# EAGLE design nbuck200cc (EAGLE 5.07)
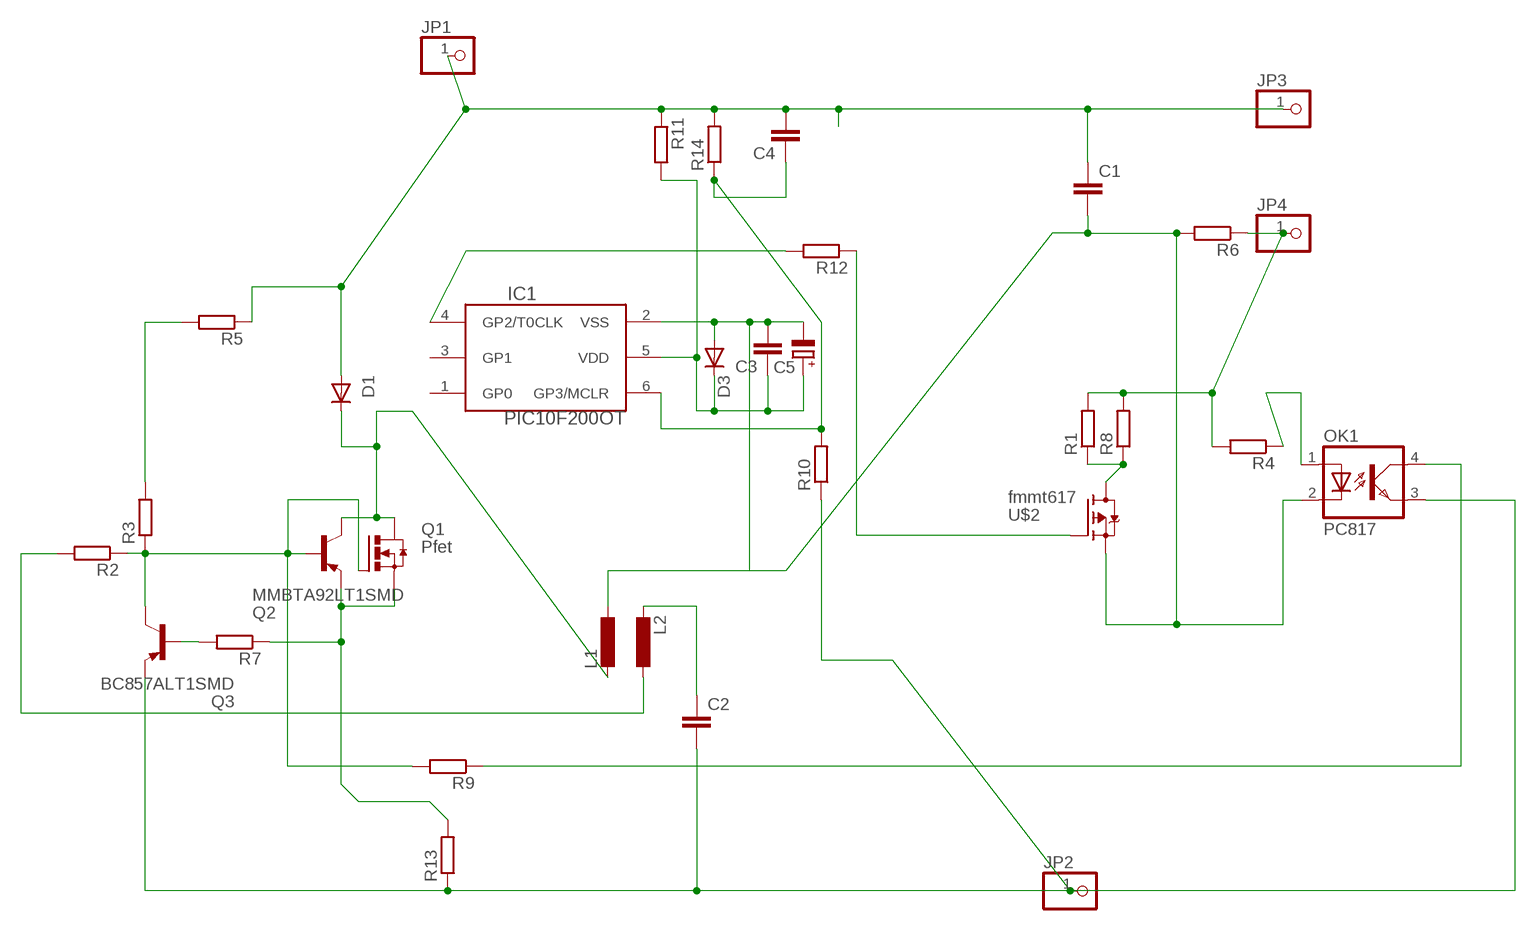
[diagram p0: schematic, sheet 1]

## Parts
C1  C-EU025-025X050  [C025-025X050]
C2  C-EUC0805  [C0805]
C3  C-EUC0805  [C0805]
C4  C-EUC1206  [C1206]
C5  CPOL-EUE2.5-5  [E2,5-5]
D1  DIODE-SMC  [SMC]
D3  DIODE-MINIMELF  [MINIMELF]
IC1  PIC10F200OT  [SOT23-6]
JP1  PINHD-1X11MM6  [1X1MM8]
JP2  PINHD-1X11MM6  [1X1MM8]
JP3  PINHD-1X11MM6  [1X1MM8]
JP4  PINHD-1X11MM6  [1X1MM8]
L1  L-EU0204/5  [0204/5]
L2  L-EU0207/10  [0207/10]
OK1  PC817  [DIL04]
Q1  Pfet  N-HEXFET_DPAK-  [TO252]
Q2  MMBTA92LT1SMD  [SOT23-BEC]
Q3  BC857ALT1SMD  [SOT23-BEC]
R1  R-EU_R2010  [R2010]
R2  R-EU_R0805  [R0805]
R3  R-EU_R1206  [R1206]
R4  R-EU_R0805  [R0805]
R5  R-EU_R1206  [R1206]
R6  R-EU_R0805  [R0805]
R7  R-EU_R1206  [R1206]
R8  R-EU_R2512  [R2512]
R9  R-EU_R0805  [R0805]
R10  R-EU_R0805  [R0805]
R11  R-EU_R1206  [R1206]
R12  R-EU_R1206  [R1206]
R13  R-EU_R1206  [R1206]
R14  R-EU_R0805  [R0805]
U$2  fmmt617  IRML6402SOT23  [SOT23]

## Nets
+: C1.1 C4.2 D1.A JP1.1 JP3.1 R5.1 R11.1 R14.2
-: C2.2 JP2.1 OK1.3(EMIT) Q3.E R10.1 R13.1
B1C2: OK1.4(COL) R9.1
C1: D1.C L1.2 Q1.3(D) Q2.C
DR+: R1.1 R8.1 U$2.3(D)
EB: Q1.2(S) Q2.E R7.1 R13.2
L-: C1.2 C3.2 C5.- D3.A IC1.2(VSS) L1.1 OK1.2(C) R6.2 U$2.2(S)
N$1: R3.2 R5.2
N$2: Q1.1(G) Q2.B Q3.C R2.1 R3.1 R9.2
N$3: Q3.B R7.2
N$4: L2.1 R2.2
N$6: C2.1 L2.2
N$7: OK1.1(A) R4.1
N$9: IC1.4(GP2/T0CLK) R12.2
N$10: C3.1 C5.+ D3.C IC1.5(VDD) R11.2
N$12: C4.1 IC1.6(GP3/MCLR) R10.2 R14.1
N$13: R12.1 U$2.1(G)
OUT-: JP4.1 R1.2 R4.2 R6.1 R8.2
Unconnected: IC1.1(GP0) IC1.3(GP1)

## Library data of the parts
C1-C4 = rcl:C-EU: CAPACITOR, European symbol
C5 = rcl:CPOL-EU: POLARIZED CAPACITOR, European symbol
D1 D3 = diode:DIODE-: DIODE
IC1 = microchip-5:PIC10F20*: uPC nW 0,25/0,5k Program Flash memory
JP1-JP4 = pinhead:PINHD-1X1: PIN HEADER
L1 L2 = rcl:L-EU: INDUCTOR, European symbol
OK1 = optocoupler:PC817: SHARP OPTO COUPLER
Q1 = transistor-power:N-HEXFET_?-*: HEXFET® Power MOSFET
Q2 = transistor-pnp:MMBTA92*: PNP Transistror
Q3 = transistor-pnp:BC857*: PNP Transistror
R1-R14 = rcl:R-EU_: RESISTOR, European symbol
U$2 = transistor-fet:IRML6402

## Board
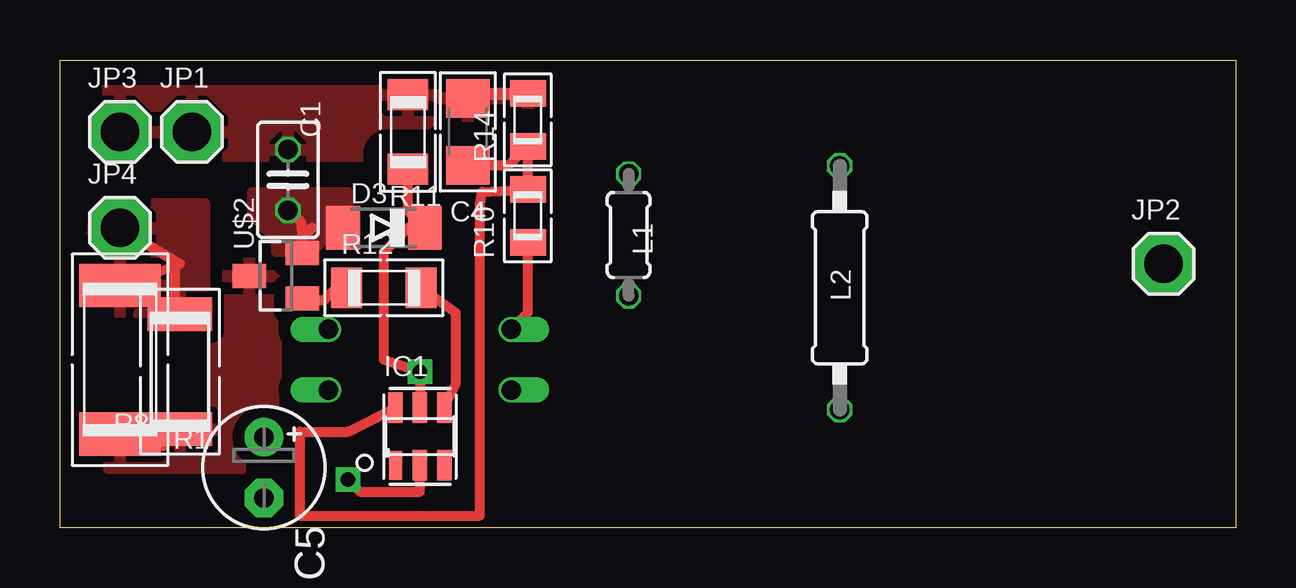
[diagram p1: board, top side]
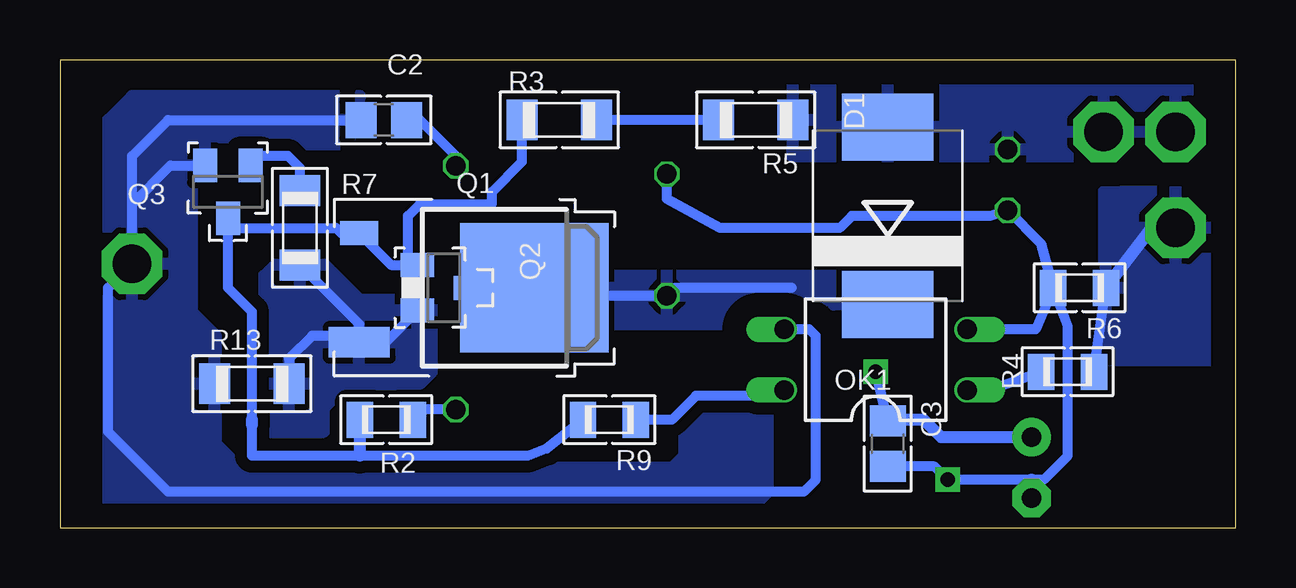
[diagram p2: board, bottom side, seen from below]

Size 49 x 19.5 mm. Coordinates in mm from the lower left corner, seen from the top.
Outline: 0,19.5 49,19.5 49,0 0,0 0,19.5
Copper layers (1*16): Top 0.035mm / dielectric 1.5mm / Bottom 0.035mm
Design rules "default *": minimum track width 10mil, minimum drill 20mil, track to track 8mil, track to pad 8mil, pad to pad 8mil, via to via 8mil, smd to smd 8mil, copper to edge 40mil, drill to drill 8mil, minimum pad ring 1mil, minimum via ring 8mil, stop-mask expansion 4mil, vias tented up to drill 0mil, thermal gap 10mil

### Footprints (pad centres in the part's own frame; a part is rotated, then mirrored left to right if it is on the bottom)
C025-025X050 = drill 0.813 octagon: 1 -1.27,0; 2 1.27,0
C0805 = smd 1.3 x 1.5: 1 -0.95,0; 2 0.95,0
C1206 = smd 1.6 x 1.8: 1 -1.4,0; 2 1.4,0
E2,5-5 = drill 0.813 pad 1.6 round: + -1.27,0 | drill 0.813 pad 1.6 octagon: - 1.27,0
SMC = smd 2.8 x 3.8: A 3.7,0; C -3.7,0
MINIMELF = smd 1.4 x 1.8: A 1.7,0; C -1.7,0
SOT23-6 = smd 0.55 x 1.2: 1 -1.016,-1.2 | smd 0.6 x 1.27: 2 0,-1.2; 3 1.016,-1.2; 4 1.016,1.2; 5 0,1.2; 6 -1.016,1.2
1X1MM8 = drill 1.6 pad 2.54 octagon: 1 0,0
0204/5 = drill 0.813 octagon: 1 -2.54,0; 2 2.54,0
0207/10 = drill 0.813 octagon: 1 -5.08,0; 2 5.08,0
DIL04 = drill 0.813 offset: 1 -1.27,-3.81; 2 1.27,-3.81; 3 1.27,3.81; 4 -1.27,3.81
TO252 = smd 1 x 1.6: 1 -2.28,-3.53 | smd 1.27 x 2.54: 2 2.28,-3.53 | smd 5.4 x 6.2: 3 0,3.77
SOT23-BEC = smd 1 x 1.4: B -0.95,-1.1; C 0,1.1; E 0.95,-1.1
R2010 = smd 1.4 x 2.7: 1 -2.4,0; 2 2.4,0
R0805 = smd 1.1 x 1.5: 1 -1.1,0; 2 1.1,0
R1206 = smd 1.3 x 1.7: 1 -1.55,0; 2 1.55,0
R2512 = smd 1.8 x 3.4: 1 -3.1,0; 2 3.1,0
SOT23 = smd 1 x 1.4: 1 -0.95,-1.1; 2 0.95,-1.1; 3 0,1.1

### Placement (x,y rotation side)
C1  9.5,14.5 270 top
C2  35.5,17 180 bottom
C3  14.5,3.5 270 bottom
C4  17,16.5 90 top
C5  8.5,2.5 270 top
D1  14.5,13 90 bottom
D3  13.5,12.5 180 top
IC1  15,3.8 0 top
JP1  5.5,16.5 0 top
JP2  46,11 0 top
JP3  2.5,16.5 0 top
JP4  2.5,12.5 0 top
L1  23.7,12.2 270 top
L2  32.5,10 90 top
OK1  15,7 90 bottom
Q1  33,10 270 bottom
Q2  33,10 270 bottom
Q3  42,14 180 bottom
R1  5,6.5 90 top
R2  35.4,4.5 0 bottom
R3  28.19,17 0 bottom
R4  7,6.5 0 bottom
R5  20,17 180 bottom
R6  6.5,10 180 bottom
R7  39,12.5 90 bottom
R8  2.5,7 90 top
R9  26.1,4.5 180 bottom
R10  19.5,13 90 top
R11  14.5,16.5 270 top
R12  13.5,10 0 top
R13  41,6 0 bottom
R14  19.5,17 90 top
U$2  9,10.5 90 top

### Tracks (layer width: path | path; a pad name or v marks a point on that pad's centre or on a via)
+
  Top 0.5: R14.2 17.2,18.1 C4.2
  pour Top (isolate 1, rank 2): 2,18.5 20,18.5 20,15.5 2,15.5
  pour Bottom (isolate 1, rank 2): 2,18.5 18.5,18.5 18.5,15.5 2,15.5
-
  Top 0.406: R10.1 19.5,8.96 OK1.3
  Bottom 0.406: C2.2 44.5,17 46,15.5 46,13.5 | 46,13.5 JP2.1 47,10 47,4 44.5,1.5 18,1.5 17.5,2 17.5,8 17.77,8.27 OK1.3 | Q3.E 44.4,15.1 46,13.5
  pour Bottom (isolate 0.5, rank 2): 36.5,18 46,18 47,17 47,1 20,1 19.5,1.5 19.5,5.5 20,6 21,6 23,4 23,3 23.5,2.5 41.5,2.5 42.5,3.5 42.5,8 43.5,9 43.5,15.5 43,16 37,16
B1C2
  Bottom 0.406: R9.1 23.5,4.5 22.5,5.5 19.04,5.5 OK1.4
C1
  Bottom 0.406: 18.5,10 23.36,10 L1.2 28.89,9.66 Q1.3 Q2.C
  pour Bottom (isolate 1, rank 2): 16,10.5 28,10.5 28,10 28,8.5 16,8.5 16,9
DR+
  Top 0.406: 7.5,10.4 U$2.3 | R1.1 4.3,3.4 R8.1
  pour Top (isolate 0.5, rank 2): 9,2.5 9,11 7,11 7,9.5 6.5,9.5 6.5,4 2,4.5 2,2.5
EB
  Bottom 0.406: R13.2 39.45,7.05 38.5,8 36.81,8 Q1.2 | Q1.2 35.43,7.72 Q2.E | Q1.2 36.53,8.48 R7.1
  pour Bottom (isolate 0.5, rank 2): 33.5,9.5 36.5,9.5 38,11 40,11 40.5,10.5 40.5,4 38,4 38,5 37,6 34,6 33.5,6.5
L-  (via drill 0.6)
  Top 0.406: C1.2 10.05,12.73 U$2.2 10.1,12.1 10.5,12.5 | v12,2 12.5,1.5 15,1.5 IC1.2
  Bottom 0.406: L1.1 23.7,13.7 21.5,12.5 16.5,12.5 16,13 10.23,13 C1.2 8.1,11.83 R6.2 | OK1.2 8.33,8.27 R6.2 | R6.2 7,8.4 7,3 8,2 8.5,2 v12,2 12.55,2.55 C3.2
  Bottom 0.5: 8.5,2 C5.-
  pour Top (no thermals): 8.5,14 12,14 12,12 11,12 10.5,11.5 9,11.5 9,12 8,13 8,14
N$1
  Bottom 0.406: R5.2 R3.2
N$2
  Bottom 0.406: 41,4.5 41,9 42,10 Q3.C 41.6,12.5 37.5,12.5 37.28,12.28 Q1.1 35.2,10.95 Q2.B 34.5,11.35 34.5,13 34,13.5 31,13.5 31,14 29.74,15.26 R3.1 | R9.2 28.7,3.3 29.5,3 36.5,3 41,3 41,4.3
  Bottom 0.5: 41,4.3 41,4.5 | 36.5,3 R2.1
N$3
  Bottom 0.406: R7.2 39,15 39.5,15.5 40.65,15.5 Q3.B
N$4
  Bottom 0.406: L2.1 33.78,4.92 R2.2
N$6
  Bottom 0.406: L2.2 32.5,15.5 34,17 C2.1
N$7
  Bottom 0.406: R4.1 10.96,5.5 OK1.1
N$9
  Top 0.406: IC1.4 16.5,6 16.5,8.95 R12.2
N$10  (via drill 0.6)
  Top 0.406: R11.2 14.5,13.2 D3.C 14.5,12.5 13.5,11.5 13.5,7 v15,6.5 IC1.5
  Bottom 0.406: C3.1 v15,6.5
  Bottom 0.5: C5.+ 12.27,3.77 13,4.5 14.45,4.5 C3.1
N$12
  Top 0.406: IC1.6 12,4 10,4 10,0.5 17.5,0.5 17.5,13.5 17.6,14 R10.2 R14.1 18.7,15.1 C4.1
N$13
  Top 0.406: R12.1 11.5,10 11,9.5 10.15,9.5 U$2.1
OUT-
  Top 0.406: JP4.1 5,11 4.79,10.88 | 4.79,10.88 R8.2 | R1.2 4.79,9.61 4.79,10.88
  Bottom 0.406: R4.2 R6.1
  Bottom 0.5: R6.1 3.5,12.5 JP4.1
  pour Bottom (isolate 1, rank 2): 1,14 5.5,14 5.5,7 1,7
  pour Top (isolate 0.5, rank 3): 1.5,13.5 6,13.5 6,9 1,9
